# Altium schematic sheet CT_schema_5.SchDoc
size 454 x 411 mm
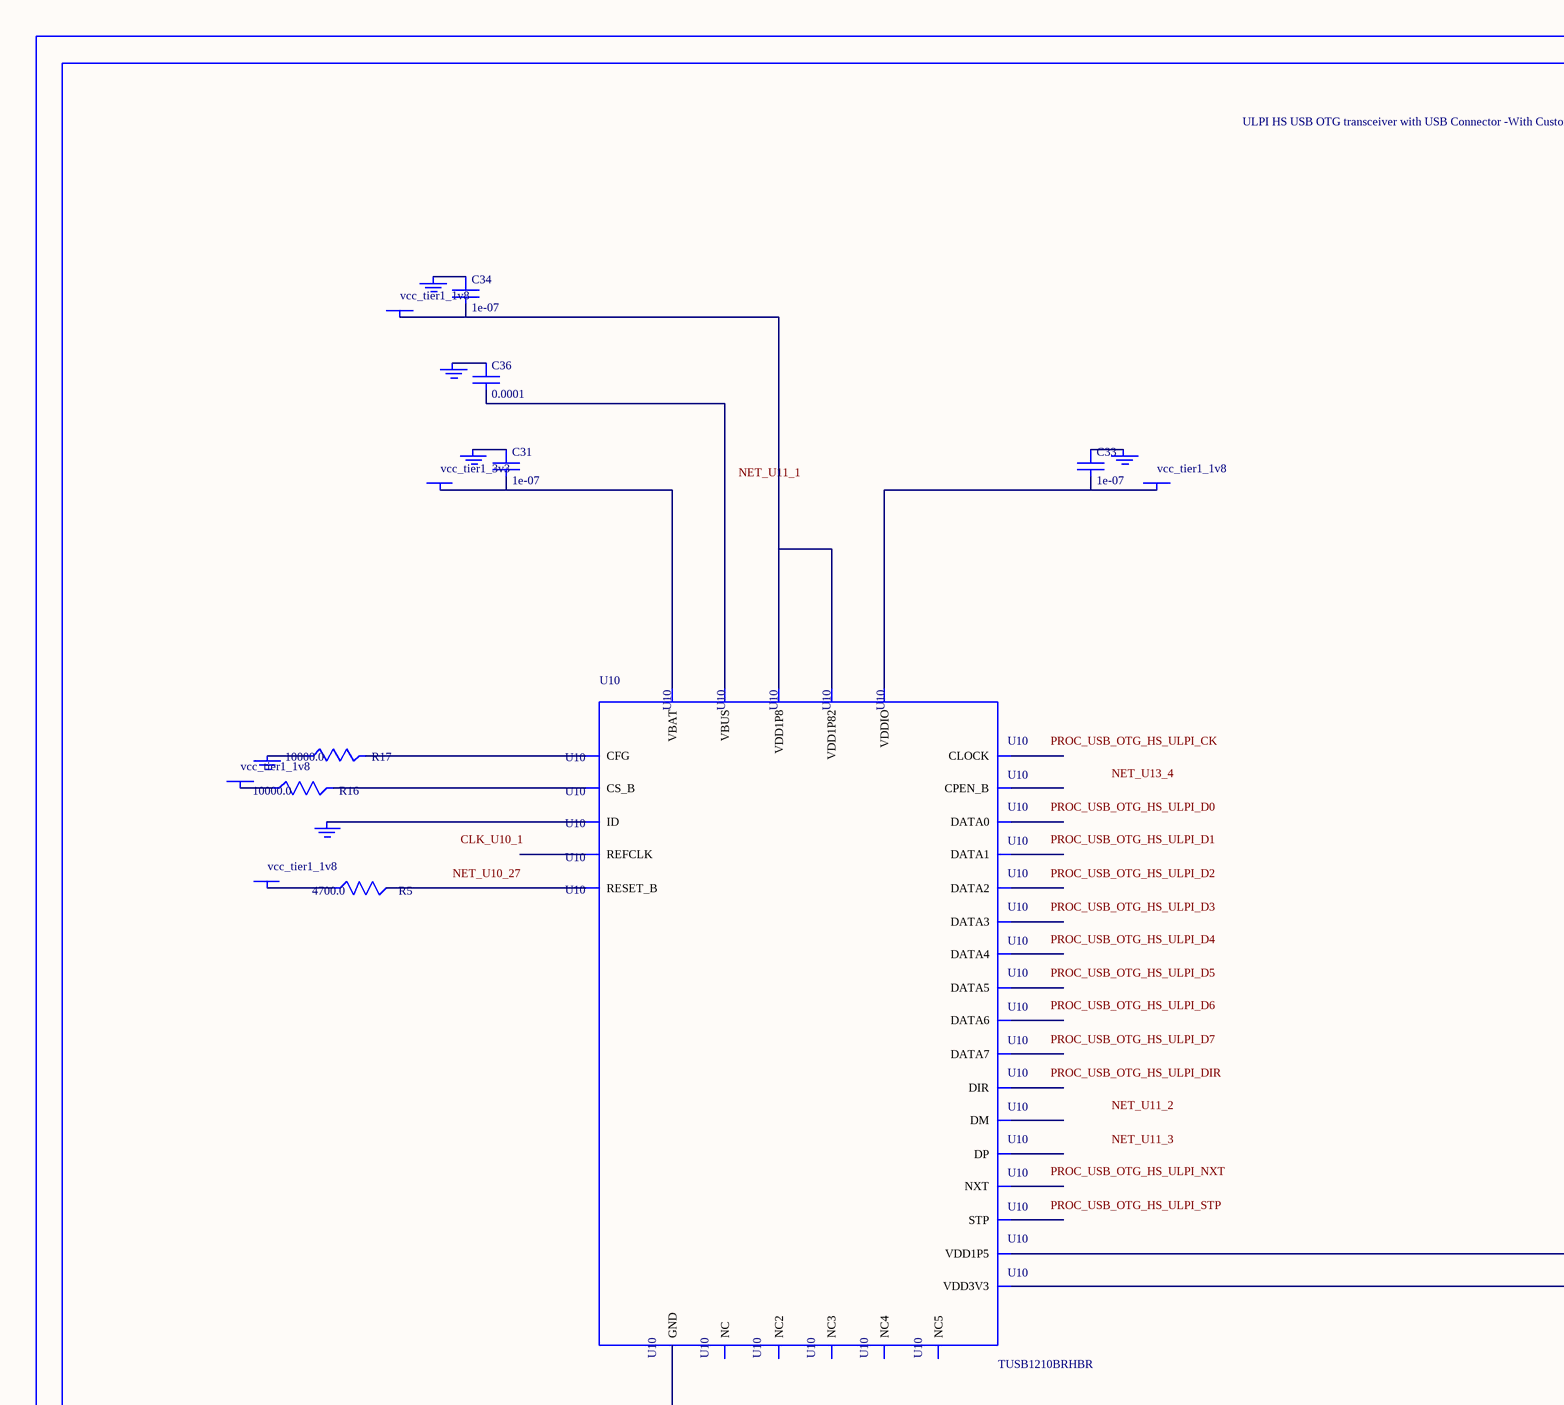
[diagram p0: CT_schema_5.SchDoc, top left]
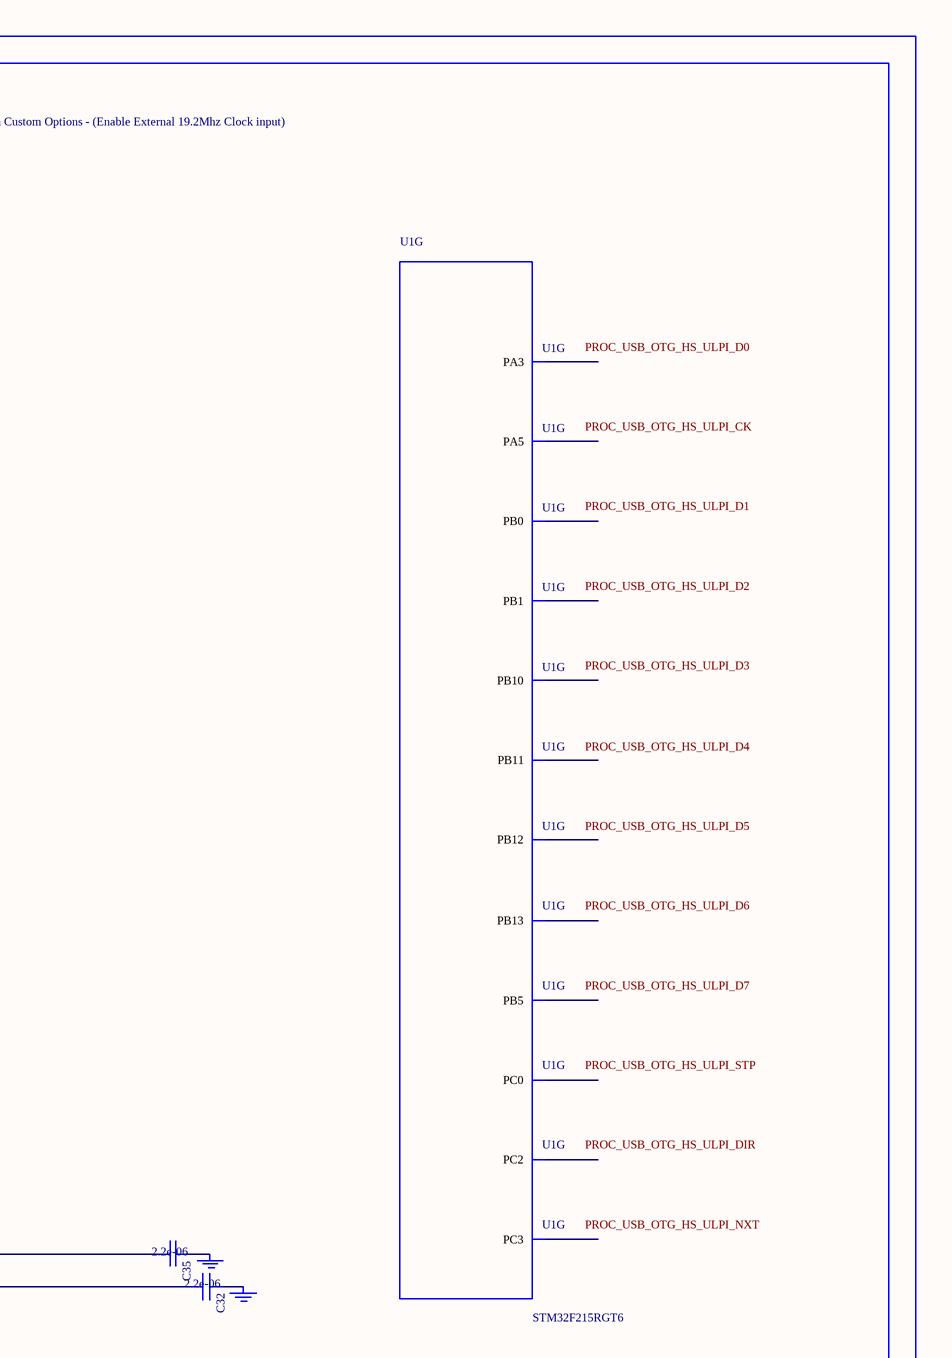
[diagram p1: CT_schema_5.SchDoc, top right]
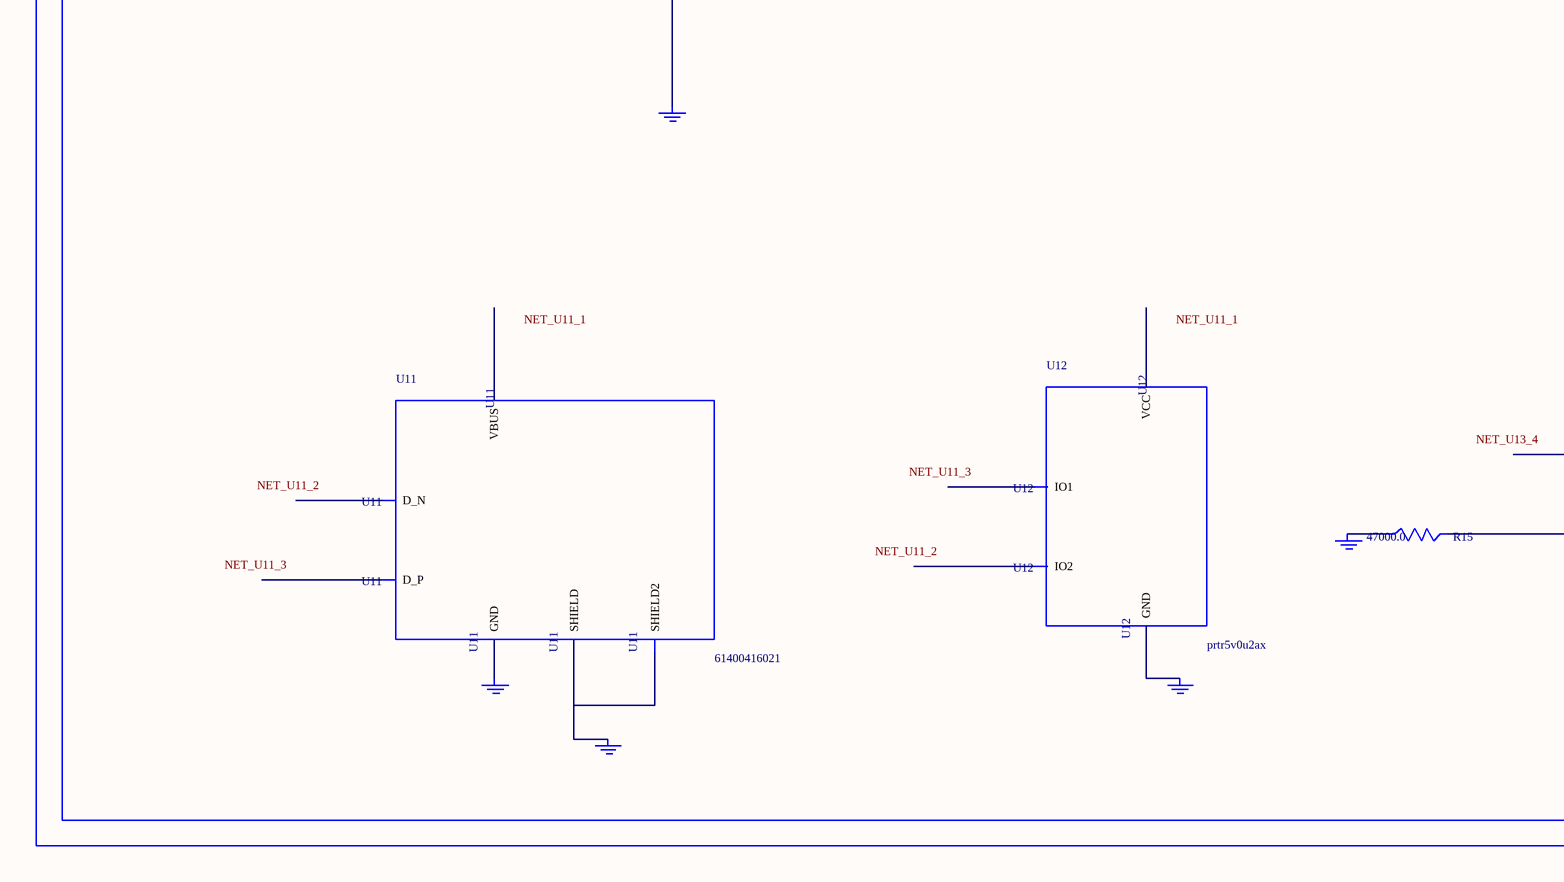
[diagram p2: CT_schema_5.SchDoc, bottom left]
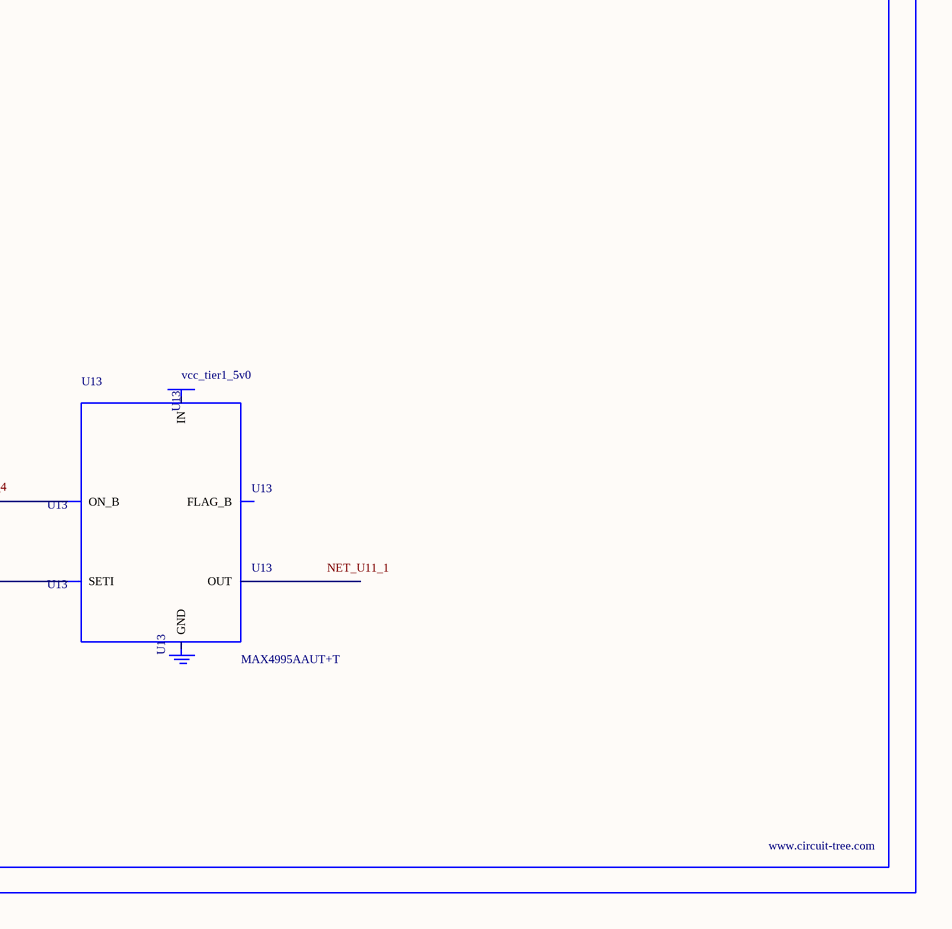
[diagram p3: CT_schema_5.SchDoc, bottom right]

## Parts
BORDER4  (no value)
C31  1e-07  [C0402]
C32  2.2e-06  [C0603]
C33  1e-07  [C0402]
C34  1e-07  [C0402]
C35  2.2e-06  [C0603]
C36  0.0001  [R0603]
GND_INSTANCE_4_0  (no value)
GND_INSTANCE_4_1  (no value)
GND_INSTANCE_4_2  (no value)
GND_INSTANCE_4_3  (no value)
GND_INSTANCE_4_4  (no value)
GND_INSTANCE_4_5  (no value)
GND_INSTANCE_4_6  (no value)
GND_INSTANCE_4_7  (no value)
GND_INSTANCE_4_8  (no value)
GND_INSTANCE_4_9  (no value)
GND_INSTANCE_4_10  (no value)
GND_INSTANCE_4_11  (no value)
GND_INSTANCE_4_12  (no value)
GND_INSTANCE_4_13  (no value)
POWER_INSTANCE_4_0  vcc_tier1_1v8
POWER_INSTANCE_4_1  vcc_tier1_3v3
POWER_INSTANCE_4_2  vcc_tier1_1v8
POWER_INSTANCE_4_3  vcc_tier1_1v8
POWER_INSTANCE_4_4  vcc_tier1_1v8
POWER_INSTANCE_4_5  vcc_tier1_5v0
R5  4700.0  [R0603]
R15  47000.0  [R0603]
R16  10000.0  [R0603]
R17  10000.0  [R0603]
U1  STM32F215RGT6  [LQFP64]  (part G of 7)
U10  TUSB1210BRHBR  [RHB32_3P45X3P45]
U11  61400416021  [USB-A-H]
U12  prtr5v0u2ax  [SOT143B]
U13  MAX4995AAUT+T  [SOT-23-6]

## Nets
NetC31_1: C31.1 GND_INSTANCE_4_3.0(GND)
NetC31_2: C31.2 POWER_INSTANCE_4_1.0(PWR) U10.21(VBAT)
NetC32_1: C32.1 GND_INSTANCE_4_2.0(GND)
NetC32_2: C32.2 U10.20(VDD3V3)
NetC33_1: C33.1 GND_INSTANCE_4_7.0(GND)
NetC33_2: C33.2 POWER_INSTANCE_4_3.0(PWR) U10.32(VDDIO)
NetC34_1: C34.1 GND_INSTANCE_4_6.0(GND)
NetC34_2: C34.2 POWER_INSTANCE_4_2.0(PWR) U10.28(VDD1P8) U10.30(VDD1P82)
NetC35_1: C35.1 GND_INSTANCE_4_0.0(GND)
NetC35_2: C35.2 U10.12(VDD1P5)
NetC36_1: C36.1 GND_INSTANCE_4_4.0(GND)
NetC36_2: C36.2 U10.22(VBUS)
NetGND_INSTANCE_4_1_0: GND_INSTANCE_4_1.0(GND) R17.1
NetGND_INSTANCE_4_5_0: GND_INSTANCE_4_5.0(GND) U10.23(ID)
NetGND_INSTANCE_4_8_0: GND_INSTANCE_4_8.0(GND) U10.33(GND)
NetGND_INSTANCE_4_9_0: GND_INSTANCE_4_9.0(GND) U11.5(SHIELD) U11.6(SHIELD2)
NetGND_INSTANCE_4_10_0: GND_INSTANCE_4_10.0(GND) U11.4(GND)
NetGND_INSTANCE_4_11_0: GND_INSTANCE_4_11.0(GND) U12.1(GND)
NetGND_INSTANCE_4_12_0: GND_INSTANCE_4_12.0(GND) R15.1
NetPOWER_INSTANCE_4_0_0: POWER_INSTANCE_4_0.0(PWR) R16.1
NetPOWER_INSTANCE_4_4_0: POWER_INSTANCE_4_4.0(PWR) R5.1
NetR5_2: R5.2 U10.27(RESET_B)
NetR15_2: R15.2 U13.3(SETI)
NetR16_2: R16.2 U10.11(CS_B)
NetR17_2: R17.2 U10.14(CFG)

Not connected (* = marked no-connect by the designer): GND_INSTANCE_4_13 0(GND); POWER_INSTANCE_4_5 0(PWR); U1 8(PC0) 10(PC2) 11(PC3) 17(PA3) 21(PA5) 26(PB0) 27(PB1) 29(PB10) 30(PB11) 33(PB12) 34(PB13) 57(PB5); U10 1(REFCLK) 2(NXT) 3(DATA0) 4(DATA1) 5(DATA2) 6(DATA3) 7(DATA4) 8(NC) 9(DATA5) 10(DATA6) 13(DATA7) 15(NC2) 16(NC3) 17(CPEN_B) 18(DP) 19(DM) 24(NC4) 25(NC5) 26(CLOCK) 29(STP) 31(DIR); U11 1(VBUS) 2(D_N) 3(D_P); U12 2(IO1) 3(IO2) 4(VCC); U13 1(OUT) 2(GND) 4(ON_B) 5(IN) 6(FLAG_B)

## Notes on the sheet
- Labels drawn without touching a wire or pin: CLK_U10_1, NET_U10_27, NET_U11_1, NET_U11_2, NET_U11_3, NET_U13_4, PROC_USB_OTG_HS_ULPI_CK, PROC_USB_OTG_HS_ULPI_D0, PROC_USB_OTG_HS_ULPI_D1, PROC_USB_OTG_HS_ULPI_D2, PROC_USB_OTG_HS_ULPI_D3, PROC_USB_OTG_HS_ULPI_D4, PROC_USB_OTG_HS_ULPI_D5, PROC_USB_OTG_HS_ULPI_D6, PROC_USB_OTG_HS_ULPI_D7, PROC_USB_OTG_HS_ULPI_DIR, PROC_USB_OTG_HS_ULPI_NXT, PROC_USB_OTG_HS_ULPI_STP

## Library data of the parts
BORDER4 = BORDER_PAGE4
C31 C33 C34 = C0402C104K3RACTU
C32 C35 = C0603C225K8RACTU
C36 = C36
GND_INSTANCE_4_0-GND_INSTANCE_4_13 = GND
POWER_INSTANCE_4_0-POWER_INSTANCE_4_5 = PWR
R5 = RC0603JR-074K7L
R15 = RC0603JR-0747KL
R16 R17 = RC0603JR-0710KL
